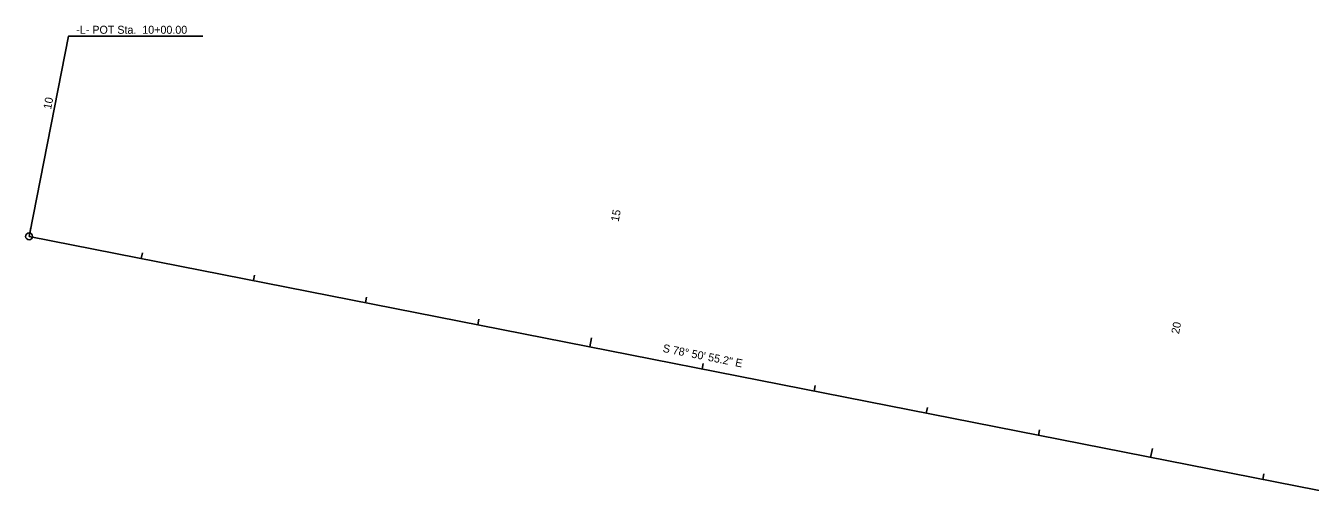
# Model space of a CAD drawing. Extents: x 1636713 to 1642783, y 841520 to 844371.
# Drawn here: x 1636713 to 1637837, y 843590 to 844007 of the extents above; entities that cross this region are included whole.
import ezdxf

# ---------------------------------------------------------------- set-up
doc = ezdxf.new("R2010")
doc.units = 0
for name, color, linetype in [('Prop Horizontal Alignment', 7, 'Continuous'), ('Prop Horizontal Alignment Direction Label', 7, 'Continuous'), ('Prop Horizontal Alignment Station Label', 7, 'Continuous'), ('Prop Horizontal Alignment Tick Label', 7, 'Continuous'), ('Prop Horizontal Alignment Tick Large', 7, 'Continuous'), ('Prop Horizontal Alignment Tick Small', 7, 'Continuous')]:
    doc.layers.add(name, color=color, linetype=linetype)

msp = doc.modelspace()

# ---------------------------------------------------------------- linework, layer by layer
at = {"layer": 'Prop Horizontal Alignment'}
msp.add_line((1636716.1, 843822.5), (1637896.4, 843589.8), dxfattribs=at)
at = {"layer": 'Prop Horizontal Alignment Station Label'}
msp.add_lwpolyline([(1636716.7, 843825.4), (1636750.7, 843997.8), (1636868.1, 843997.8)], dxfattribs=at)
msp.add_circle((1636716.1, 843822.5), 3, dxfattribs=at)
at = {"layer": 'Prop Horizontal Alignment Tick Large'}
for p, q in [((1636716.1, 843822.5), (1636717.7, 843830.3)), ((1637206.7, 843725.8), (1637208.2, 843733.6)), ((1637697.2, 843629.1), (1637698.8, 843636.9))]:
    msp.add_line(p, q, dxfattribs=at)
at = {"layer": 'Prop Horizontal Alignment Tick Small'}
for p, q in [((1636814.2, 843803.1), (1636815.2, 843808)), ((1636912.3, 843783.8), (1636913.3, 843788.7)), ((1637010.5, 843764.5), (1637011.4, 843769.4)), ((1637108.6, 843745.1), (1637109.5, 843750)), ((1637304.8, 843706.4), (1637305.8, 843711.3)), ((1637402.9, 843687.1), (1637403.9, 843692)), ((1637501, 843667.8), (1637502, 843672.7)), ((1637599.1, 843648.4), (1637600.1, 843653.3)), ((1637795.4, 843609.7), (1637796.3, 843614.6))]:
    msp.add_line(p, q, dxfattribs=at)

# ---------------------------------------------------------------- texts
at = {"layer": 'Prop Horizontal Alignment Direction Label'}
msp.add_text('S 78%%d 50\' 55.2" E', height=7, rotation=348.8487, dxfattribs=at).set_placement((1637270, 843721.5))
at = {"layer": 'Prop Horizontal Alignment Station Label'}
msp.add_text('-L- POT Sta.  10+00.00', height=7, rotation=360, dxfattribs=at).set_placement((1636757.4, 843999.8))
at = {"layer": 'Prop Horizontal Alignment Tick Label'}
for s, p in [('10', (1636735.3, 843933.3)), ('15', (1637231.8, 843835)), ('20', (1637722, 843736.7))]:
    msp.add_text(s, height=7, rotation=78.8487, dxfattribs=at).set_placement(p)

doc.saveas('drawing.dxf')
